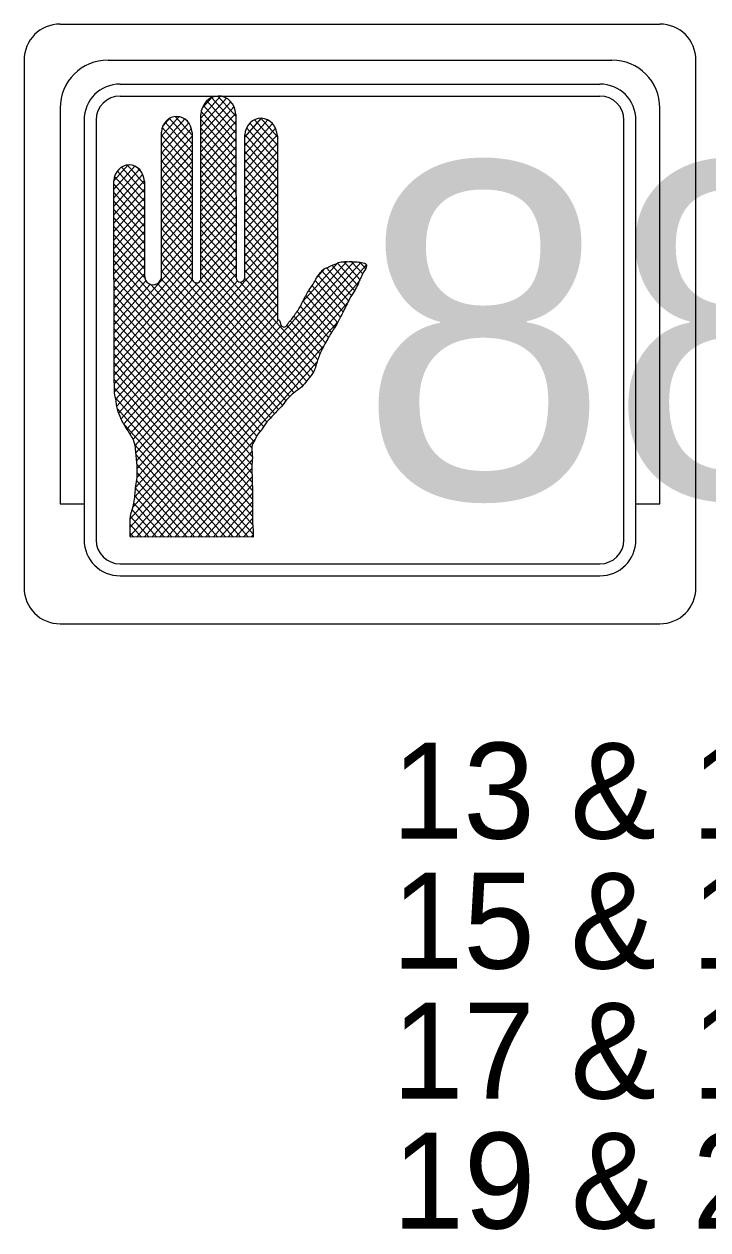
# Model space of a CAD drawing. Extents: x 1281646 to 1282646, y 1891886 to 1892526.
# Drawn here: x 1281920.8 to 1281949.3, y 1892029.8 to 1892080.1 of the extents above; entities that cross this region are included whole.
import ezdxf

# ---------------------------------------------------------------- set-up
doc = ezdxf.new("R2010")
doc.units = 0
doc.layers.add('T_Drafting', color=7, linetype='Continuous')
doc.layers.add('T_Notes', color=7, linetype='Continuous')

msp = doc.modelspace()

# ---------------------------------------------------------------- linework, layer by layer
at = {"layer": 'T_Drafting'}
for p, q in [((1281922.341, 1892080.09), (1281947.341, 1892080.09)), ((1281920.841, 1892078.59), (1281920.841, 1892056.59)), ((1281924.341, 1892078.59), (1281945.341, 1892078.59)), ((1281948.841, 1892056.59), (1281948.841, 1892078.59)), ((1281924.841, 1892077.59), (1281944.841, 1892077.59)), ((1281924.841, 1892077.09), (1281944.841, 1892077.09)), ((1281928.205, 1892076.174), (1281929.027, 1892077.087)), ((1281928.913, 1892077.093), (1281929.668, 1892076.254)), ((1281922.341, 1892076.59), (1281922.341, 1892060.09)), ((1281928.205, 1892075.821), (1281929.27, 1892077.004)), ((1281928.206, 1892075.468), (1281929.455, 1892076.856)), ((1281928.206, 1892075.115), (1281929.589, 1892076.651)), ((1281928.259, 1892076.587), (1281928.66, 1892077.033)), ((1281928.311, 1892076.702), (1281929.67, 1892075.192)), ((1281928.456, 1892076.894), (1281929.669, 1892075.546)), ((1281928.652, 1892077.029), (1281929.669, 1892075.9)), ((1281929.38, 1892076.928), (1281929.521, 1892076.771)), ((1281947.341, 1892060.09), (1281947.341, 1892076.59)), ((1281923.341, 1892076.09), (1281923.341, 1892058.59)), ((1281923.841, 1892076.09), (1281923.841, 1892058.59)), ((1281926.567, 1892075.414), (1281927.304, 1892076.234)), ((1281926.567, 1892075.061), (1281927.536, 1892076.138)), ((1281926.624, 1892075.832), (1281926.935, 1892076.177)), ((1281926.894, 1892076.154), (1281927.84, 1892075.103)), ((1281927.136, 1892076.239), (1281927.84, 1892075.457)), ((1281927.561, 1892076.12), (1281927.73, 1892075.932)), ((1281928.213, 1892069.489), (1281928.205, 1892076.316)), ((1281928.205, 1892076.112), (1281929.67, 1892074.484)), ((1281928.207, 1892074.762), (1281929.664, 1892076.381)), ((1281928.22, 1892076.449), (1281929.67, 1892074.838)), ((1281929.668, 1892076.335), (1281929.676, 1892069.557)), ((1281930.035, 1892075.379), (1281930.741, 1892076.163)), ((1281930.036, 1892075.026), (1281930.998, 1892076.095)), ((1281930.442, 1892076.101), (1281931.397, 1892075.041)), ((1281930.704, 1892076.164), (1281931.396, 1892075.395)), ((1281945.841, 1892058.59), (1281945.841, 1892076.09)), ((1281946.341, 1892058.59), (1281946.341, 1892076.09)), ((1281926.573, 1892069.617), (1281926.567, 1892075.582)), ((1281926.568, 1892074.708), (1281927.705, 1892075.972)), ((1281926.568, 1892074.355), (1281927.813, 1892075.739)), ((1281926.602, 1892075.772), (1281927.841, 1892074.395)), ((1281926.719, 1892075.996), (1281927.841, 1892074.749)), ((1281928.206, 1892075.758), (1281929.671, 1892074.13)), ((1281928.207, 1892074.409), (1281929.669, 1892076.033)), ((1281928.207, 1892074.055), (1281929.669, 1892075.679)), ((1281930.036, 1892074.673), (1281931.187, 1892075.952)), ((1281930.036, 1892074.32), (1281931.323, 1892075.749)), ((1281930.112, 1892075.761), (1281931.397, 1892074.333)), ((1281930.25, 1892075.961), (1281931.397, 1892074.687)), ((1281926.567, 1892075.457), (1281927.842, 1892074.041)), ((1281926.567, 1892075.103), (1281927.842, 1892073.687)), ((1281926.568, 1892074.002), (1281927.84, 1892075.415)), ((1281927.839, 1892075.568), (1281927.846, 1892069.522)), ((1281928.206, 1892075.404), (1281929.671, 1892073.776)), ((1281928.208, 1892073.702), (1281929.669, 1892075.326)), ((1281930.042, 1892069.525), (1281930.035, 1892075.473)), ((1281930.036, 1892075.139), (1281931.398, 1892073.625)), ((1281930.037, 1892075.491), (1281931.398, 1892073.979)), ((1281930.037, 1892073.967), (1281931.394, 1892075.474)), ((1281930.037, 1892073.614), (1281931.397, 1892075.124)), ((1281931.396, 1892075.426), (1281931.405, 1892067.769)), ((1281926.568, 1892074.749), (1281927.842, 1892073.333)), ((1281926.569, 1892073.649), (1281927.84, 1892075.062)), ((1281926.569, 1892073.296), (1281927.841, 1892074.709)), ((1281928.206, 1892075.05), (1281929.672, 1892073.422)), ((1281928.207, 1892074.696), (1281929.672, 1892073.068)), ((1281928.208, 1892073.349), (1281929.67, 1892074.973)), ((1281928.209, 1892072.996), (1281929.67, 1892074.62)), ((1281930.036, 1892074.785), (1281931.398, 1892073.271)), ((1281930.038, 1892073.261), (1281931.397, 1892074.771)), ((1281924.579, 1892073.559), (1281925.174, 1892074.221)), ((1281924.579, 1892073.206), (1281925.449, 1892074.173)), ((1281924.899, 1892074.129), (1281925.852, 1892073.069)), ((1281925.138, 1892074.217), (1281925.852, 1892073.423)), ((1281925.541, 1892074.122), (1281925.763, 1892073.876)), ((1281926.568, 1892074.395), (1281927.843, 1892072.979)), ((1281926.57, 1892072.943), (1281927.841, 1892074.356)), ((1281928.207, 1892074.342), (1281929.672, 1892072.714)), ((1281928.209, 1892072.643), (1281929.671, 1892074.267)), ((1281930.036, 1892074.431), (1281931.399, 1892072.917)), ((1281930.037, 1892074.077), (1281931.399, 1892072.563)), ((1281930.038, 1892072.907), (1281931.397, 1892074.418)), ((1281930.038, 1892072.554), (1281931.398, 1892074.065)), ((1281924.588, 1892065.318), (1281924.578, 1892073.561)), ((1281924.579, 1892072.853), (1281925.645, 1892074.037)), ((1281924.58, 1892072.5), (1281925.783, 1892073.836)), ((1281924.58, 1892072.146), (1281925.851, 1892073.559)), ((1281924.611, 1892073.741), (1281925.853, 1892072.361)), ((1281924.725, 1892073.968), (1281925.853, 1892072.715)), ((1281926.568, 1892074.041), (1281927.843, 1892072.625)), ((1281926.569, 1892073.687), (1281927.844, 1892072.271)), ((1281926.57, 1892072.59), (1281927.842, 1892074.002)), ((1281926.57, 1892072.236), (1281927.842, 1892073.649)), ((1281928.208, 1892073.988), (1281929.673, 1892072.36)), ((1281928.208, 1892073.634), (1281929.673, 1892072.006)), ((1281928.209, 1892072.29), (1281929.671, 1892073.914)), ((1281928.21, 1892071.937), (1281929.671, 1892073.561)), ((1281930.037, 1892073.723), (1281931.4, 1892072.209)), ((1281930.039, 1892072.201), (1281931.398, 1892073.711)), ((1281924.579, 1892073.424), (1281925.854, 1892072.007)), ((1281924.579, 1892073.07), (1281925.854, 1892071.653)), ((1281924.581, 1892071.793), (1281925.852, 1892073.206)), ((1281925.852, 1892073.547), (1281925.856, 1892069.616)), ((1281926.569, 1892073.333), (1281927.844, 1892071.917)), ((1281926.571, 1892071.883), (1281927.842, 1892073.296)), ((1281928.208, 1892073.28), (1281929.674, 1892071.652)), ((1281928.21, 1892071.584), (1281929.672, 1892073.208)), ((1281930.038, 1892073.369), (1281931.4, 1892071.855)), ((1281930.039, 1892071.848), (1281931.398, 1892073.358)), ((1281924.58, 1892072.716), (1281925.854, 1892071.299)), ((1281924.581, 1892071.44), (1281925.853, 1892072.853)), ((1281926.57, 1892072.979), (1281927.844, 1892071.563)), ((1281926.57, 1892072.625), (1281927.845, 1892071.209)), ((1281926.571, 1892071.53), (1281927.843, 1892072.943)), ((1281926.572, 1892071.177), (1281927.843, 1892072.59)), ((1281928.209, 1892072.926), (1281929.674, 1892071.298)), ((1281928.209, 1892072.572), (1281929.674, 1892070.944)), ((1281928.211, 1892071.231), (1281929.672, 1892072.854)), ((1281930.038, 1892073.015), (1281931.4, 1892071.501)), ((1281930.038, 1892072.661), (1281931.401, 1892071.147)), ((1281930.04, 1892071.495), (1281931.399, 1892073.005)), ((1281930.04, 1892071.142), (1281931.399, 1892072.652)), ((1281924.58, 1892072.362), (1281925.855, 1892070.945)), ((1281924.581, 1892071.087), (1281925.853, 1892072.5)), ((1281924.582, 1892070.734), (1281925.853, 1892072.147)), ((1281926.57, 1892072.271), (1281927.845, 1892070.855)), ((1281926.572, 1892070.824), (1281927.844, 1892072.237)), ((1281928.21, 1892072.218), (1281929.675, 1892070.59)), ((1281928.211, 1892070.877), (1281929.673, 1892072.501)), ((1281928.211, 1892070.524), (1281929.673, 1892072.148)), ((1281930.039, 1892072.307), (1281931.401, 1892070.793)), ((1281930.04, 1892070.789), (1281931.399, 1892072.299)), ((1281924.58, 1892072.008), (1281925.855, 1892070.591)), ((1281924.581, 1892071.654), (1281925.856, 1892070.237)), ((1281924.582, 1892070.381), (1281925.854, 1892071.794)), ((1281926.571, 1892071.917), (1281927.846, 1892070.501)), ((1281926.571, 1892071.563), (1281927.846, 1892070.147)), ((1281926.572, 1892070.471), (1281927.844, 1892071.884)), ((1281928.21, 1892071.864), (1281929.675, 1892070.236)), ((1281928.212, 1892070.171), (1281929.673, 1892071.795)), ((1281930.039, 1892071.953), (1281931.401, 1892070.439)), ((1281930.04, 1892071.599), (1281931.402, 1892070.085)), ((1281930.041, 1892070.436), (1281931.4, 1892071.946)), ((1281930.041, 1892070.083), (1281931.4, 1892071.592)), ((1281924.581, 1892071.3), (1281925.856, 1892069.883)), ((1281924.582, 1892070.028), (1281925.854, 1892071.441)), ((1281924.583, 1892069.674), (1281925.855, 1892071.088)), ((1281926.572, 1892071.209), (1281927.846, 1892069.793)), ((1281926.573, 1892070.118), (1281927.844, 1892071.531)), ((1281926.573, 1892069.765), (1281927.845, 1892071.178)), ((1281928.209, 1892069.461), (1281929.674, 1892071.089)), ((1281928.21, 1892071.51), (1281929.675, 1892069.882)), ((1281928.211, 1892071.156), (1281929.67, 1892069.534)), ((1281928.212, 1892069.818), (1281929.674, 1892071.442)), ((1281930.04, 1892071.245), (1281931.402, 1892069.731)), ((1281930.042, 1892069.729), (1281931.401, 1892071.239)), ((1281924.581, 1892070.946), (1281925.868, 1892069.516)), ((1281924.582, 1892070.592), (1281930.959, 1892063.506)), ((1281924.583, 1892069.321), (1281925.855, 1892070.734)), ((1281924.585, 1892067.203), (1281927.845, 1892070.825)), ((1281924.6, 1892065.097), (1281929.675, 1892070.736)), ((1281924.88, 1892063.641), (1281931.401, 1892070.886)), ((1281926.572, 1892070.855), (1281927.862, 1892069.422)), ((1281928.211, 1892070.802), (1281932.905, 1892065.586)), ((1281930.04, 1892070.891), (1281931.402, 1892069.377)), ((1281924.582, 1892070.238), (1281930.812, 1892063.316)), ((1281924.584, 1892068.968), (1281925.855, 1892070.381)), ((1281924.586, 1892066.849), (1281927.846, 1892070.471)), ((1281924.586, 1892066.496), (1281927.846, 1892070.118)), ((1281924.611, 1892064.756), (1281929.675, 1892070.383)), ((1281925.004, 1892063.425), (1281931.401, 1892070.533)), ((1281925.129, 1892063.21), (1281931.402, 1892070.18)), ((1281925.263, 1892059.117), (1281935.11, 1892070.057)), ((1281925.274, 1892059.482), (1281934.879, 1892070.154)), ((1281925.379, 1892059.952), (1281934.59, 1892070.187)), ((1281925.449, 1892060.384), (1281934.272, 1892070.187)), ((1281926.572, 1892070.501), (1281931.919, 1892064.561)), ((1281926.573, 1892070.147), (1281931.762, 1892064.382)), ((1281928.212, 1892070.448), (1281932.765, 1892065.388)), ((1281928.212, 1892070.094), (1281932.615, 1892065.201)), ((1281930.041, 1892070.537), (1281931.403, 1892069.023)), ((1281930.041, 1892070.183), (1281931.403, 1892068.669)), ((1281932.443, 1892068.508), (1281933.898, 1892070.126)), ((1281933.907, 1892070.13), (1281934.739, 1892069.206)), ((1281934.174, 1892070.187), (1281934.84, 1892069.447)), ((1281934.492, 1892070.187), (1281934.953, 1892069.674)), ((1281934.834, 1892070.161), (1281935.064, 1892069.905)), ((1281924.583, 1892069.884), (1281930.678, 1892063.112)), ((1281924.584, 1892068.615), (1281925.856, 1892070.028)), ((1281924.584, 1892068.262), (1281925.856, 1892069.675)), ((1281924.587, 1892066.143), (1281927.846, 1892069.765)), ((1281924.66, 1892064.456), (1281929.675, 1892070.03)), ((1281924.709, 1892064.158), (1281929.676, 1892069.676)), ((1281925.253, 1892062.994), (1281931.402, 1892069.827)), ((1281926.573, 1892069.793), (1281931.606, 1892064.202)), ((1281928.212, 1892069.74), (1281932.459, 1892065.022)), ((1281930.042, 1892069.829), (1281931.404, 1892068.315)), ((1281933.044, 1892069.53), (1281933.386, 1892069.91)), ((1281933.099, 1892069.613), (1281934.254, 1892068.33)), ((1281933.25, 1892069.799), (1281934.366, 1892068.559)), ((1281933.448, 1892069.933), (1281934.489, 1892068.777)), ((1281933.672, 1892070.038), (1281934.617, 1892068.988)), ((1281924.583, 1892069.53), (1281930.534, 1892062.918)), ((1281924.583, 1892069.176), (1281930.422, 1892062.688)), ((1281924.585, 1892067.909), (1281925.919, 1892069.392)), ((1281924.585, 1892067.556), (1281926.1, 1892069.239)), ((1281924.587, 1892065.79), (1281927.86, 1892069.427)), ((1281924.587, 1892065.437), (1281928.07, 1892069.307)), ((1281924.773, 1892063.875), (1281929.734, 1892069.387)), ((1281925.264, 1892058.764), (1281934.803, 1892069.363)), ((1281925.374, 1892062.775), (1281931.402, 1892069.474)), ((1281925.468, 1892062.526), (1281931.403, 1892069.12)), ((1281926.124, 1892069.231), (1281931.119, 1892063.682)), ((1281926.402, 1892069.277), (1281931.281, 1892063.855)), ((1281926.548, 1892069.468), (1281931.444, 1892064.028)), ((1281927.954, 1892069.32), (1281932.09, 1892064.724)), ((1281928.192, 1892069.409), (1281932.278, 1892064.869)), ((1281929.849, 1892069.336), (1281932.999, 1892065.836)), ((1281930.035, 1892069.483), (1281931.404, 1892067.962)), ((1281932.847, 1892069.186), (1281934.025, 1892067.878)), ((1281932.968, 1892069.405), (1281934.142, 1892068.101)), ((1281924.584, 1892068.822), (1281930.339, 1892062.428)), ((1281925.503, 1892062.212), (1281931.403, 1892068.767)), ((1281932.463, 1892068.552), (1281933.654, 1892067.229)), ((1281932.584, 1892068.772), (1281933.784, 1892067.438)), ((1281932.708, 1892068.988), (1281933.906, 1892067.657)), ((1281924.584, 1892068.468), (1281930.35, 1892062.062)), ((1281924.585, 1892068.114), (1281930.335, 1892061.724)), ((1281925.529, 1892058.705), (1281934.327, 1892068.481)), ((1281925.534, 1892061.892), (1281931.403, 1892068.414)), ((1281925.553, 1892061.56), (1281931.404, 1892068.061)), ((1281932.219, 1892068.116), (1281933.401, 1892066.803)), ((1281932.358, 1892068.316), (1281933.523, 1892067.021)), ((1281924.585, 1892067.76), (1281930.336, 1892061.37)), ((1281925.494, 1892060.787), (1281931.566, 1892067.534)), ((1281925.55, 1892061.203), (1281931.45, 1892067.758)), ((1281925.847, 1892058.705), (1281933.909, 1892067.662)), ((1281931.788, 1892067.534), (1281933.08, 1892066.099)), ((1281931.937, 1892067.722), (1281933.175, 1892066.347)), ((1281932.085, 1892067.911), (1281933.283, 1892066.581)), ((1281924.585, 1892067.406), (1281930.352, 1892060.998)), ((1281924.586, 1892067.052), (1281930.354, 1892060.643)), ((1281924.586, 1892066.698), (1281930.354, 1892060.289)), ((1281926.166, 1892058.706), (1281933.326, 1892066.662)), ((1281924.586, 1892066.344), (1281930.355, 1892059.935)), ((1281924.587, 1892065.99), (1281930.357, 1892059.579)), ((1281924.587, 1892065.636), (1281930.371, 1892059.21)), ((1281926.485, 1892058.706), (1281933.043, 1892065.994)), ((1281924.59, 1892065.28), (1281930.391, 1892058.834)), ((1281924.602, 1892064.912), (1281930.183, 1892058.711)), ((1281924.652, 1892064.504), (1281929.865, 1892058.711)), ((1281924.724, 1892064.07), (1281929.548, 1892058.71)), ((1281925.035, 1892063.371), (1281929.23, 1892058.71)), ((1281925.466, 1892062.538), (1281928.912, 1892058.709)), ((1281926.803, 1892058.706), (1281930.476, 1892062.787)), ((1281925.512, 1892062.134), (1281928.594, 1892058.709)), ((1281927.122, 1892058.707), (1281930.345, 1892062.289)), ((1281925.544, 1892061.745), (1281928.276, 1892058.709)), ((1281927.44, 1892058.707), (1281930.343, 1892061.933)), ((1281927.759, 1892058.708), (1281930.334, 1892061.569)), ((1281925.535, 1892061.047), (1281927.641, 1892058.708)), ((1281925.556, 1892061.378), (1281927.959, 1892058.708)), ((1281928.078, 1892058.708), (1281930.342, 1892061.224)), ((1281925.488, 1892060.746), (1281927.323, 1892058.707)), ((1281928.396, 1892058.709), (1281930.353, 1892060.884)), ((1281928.715, 1892058.709), (1281930.354, 1892060.53)), ((1281922.341, 1892060.09), (1281923.341, 1892060.09)), ((1281925.418, 1892060.116), (1281926.687, 1892058.706)), ((1281925.454, 1892060.431), (1281927.005, 1892058.707)), ((1281929.033, 1892058.71), (1281930.354, 1892060.177)), ((1281946.341, 1892060.09), (1281947.341, 1892060.09)), ((1281925.279, 1892059.564), (1281926.052, 1892058.705)), ((1281925.344, 1892059.846), (1281926.37, 1892058.706)), ((1281929.352, 1892058.71), (1281930.355, 1892059.824)), ((1281925.265, 1892059.227), (1281925.734, 1892058.705)), ((1281929.671, 1892058.71), (1281930.36, 1892059.476)), ((1281929.989, 1892058.711), (1281930.374, 1892059.139)), ((1281925.264, 1892058.874), (1281925.416, 1892058.705)), ((1281925.289, 1892058.704), (1281925.264, 1892058.736)), ((1281930.369, 1892058.711), (1281925.289, 1892058.704)), ((1281930.308, 1892058.711), (1281930.391, 1892058.804)), ((1281930.392, 1892058.705), (1281930.369, 1892058.711)), ((1281924.841, 1892057.59), (1281944.841, 1892057.59)), ((1281924.841, 1892057.09), (1281944.841, 1892057.09)), ((1281922.341, 1892055.09), (1281947.341, 1892055.09))]:
    msp.add_line(p, q, dxfattribs=at)
for centre, radius, start, end in [((1281922.341, 1892078.59), 1.5, 90, 180), ((1281947.341, 1892078.59), 1.5, 0, 90), ((1281924.341, 1892076.59), 2, 90, 180), ((1281945.341, 1892076.59), 2, 0, 90), ((1281924.841, 1892076.09), 1.5, 90, 180), ((1281944.841, 1892076.09), 1.5, 0, 90), ((1281924.841, 1892076.09), 1, 90, 180), ((1281944.841, 1892076.09), 1, 0, 90), ((1281924.841, 1892058.59), 1.5, 180, 270), ((1281924.841, 1892058.59), 1, 180, 270), ((1281944.841, 1892058.59), 1.5, 270, 0), ((1281944.841, 1892058.59), 1, 270, 0), ((1281922.341, 1892056.59), 1.5, 180, 270), ((1281947.341, 1892056.59), 1.5, 270, 0)]:
    msp.add_arc(centre, radius, start, end, dxfattribs=at)
for centre, major_axis, start_param, end_param in [((1281928.937, 1892076.279), (0, -0.814), 1.640121, 4.665593), ((1281927.203, 1892075.534), (0, -0.709), 1.618611, 4.644084), ((1281930.714, 1892075.406), (0, -0.758), 1.597842, 4.623315), ((1281925.215, 1892073.513), (0, -0.709), 1.618611, 4.644084), ((1281926.215, 1892069.617), (0, -0.398), 4.713646, 7.855239), ((1281929.856, 1892069.543), (0, -0.207), 4.624552, 7.766145), ((1281928.03, 1892069.506), (0, -0.204), 4.633755, 7.775348)]:
    msp.add_ellipse(centre, major_axis=major_axis, ratio=0.9, start_param=start_param, end_param=end_param, dxfattribs=at)
for points in [[(1281931.404, 1892067.77), (1281931.455, 1892067.756), (1281931.525, 1892067.601), (1281931.613, 1892067.482), (1281931.665, 1892067.463), (1281931.753, 1892067.482), (1281931.807, 1892067.562), (1281931.965, 1892067.757), (1281932.088, 1892067.915), (1281932.158, 1892068.031), (1281932.228, 1892068.129), (1281932.351, 1892068.305), (1281932.421, 1892068.462), (1281932.526, 1892068.676), (1281932.597, 1892068.795), (1281932.72, 1892069.009), (1281932.86, 1892069.206), (1281932.966, 1892069.401), (1281933.088, 1892069.596), (1281933.195, 1892069.733), (1281933.351, 1892069.891), (1281933.544, 1892069.97), (1281933.651, 1892070.029), (1281933.809, 1892070.086), (1281933.949, 1892070.146), (1281934.162, 1892070.187), (1281934.337, 1892070.187), (1281934.566, 1892070.187), (1281934.777, 1892070.168), (1281935.023, 1892070.129), (1281935.093, 1892070.088), (1281935.11, 1892070.031), (1281935.006, 1892069.777), (1281934.935, 1892069.639), (1281934.866, 1892069.501), (1281934.795, 1892069.346), (1281934.759, 1892069.248), (1281934.619, 1892068.992), (1281934.41, 1892068.641), (1281934.128, 1892068.074), (1281933.777, 1892067.426), (1281933.497, 1892066.976), (1281933.338, 1892066.683), (1281933.198, 1892066.407), (1281933.116, 1892066.19), (1281933.073, 1892066.079), (1281932.916, 1892065.607), (1281932.671, 1892065.274), (1281932.477, 1892065.039), (1281932.197, 1892064.803), (1281932.02, 1892064.666), (1281931.564, 1892064.156), (1281931.16, 1892063.727), (1281930.897, 1892063.432), (1281930.668, 1892063.098), (1281930.554, 1892062.953), (1281930.458, 1892062.748), (1281930.352, 1892062.55), (1281930.352, 1892062.12), (1281930.335, 1892061.734), (1281930.336, 1892061.38), (1281930.353, 1892060.912), (1281930.354, 1892060.462), (1281930.355, 1892059.738), (1281930.373, 1892059.155), (1281930.391, 1892058.939), (1281930.391, 1892058.781), (1281930.391, 1892058.706)], [(1281925.264, 1892058.736), (1281925.263, 1892059.05), (1281925.28, 1892059.577), (1281925.42, 1892060.126), (1281925.489, 1892060.752), (1281925.542, 1892061.104), (1281925.541, 1892061.789), (1281925.487, 1892062.356), (1281925.434, 1892062.649), (1281925.171, 1892063.137), (1281924.888, 1892063.627), (1281924.729, 1892064.038), (1281924.658, 1892064.467), (1281924.604, 1892064.8), (1281924.604, 1892065.014), (1281924.588, 1892065.318)]]:
    msp.add_spline(points, degree=3, dxfattribs=at)

# ---------------------------------------------------------------- texts
msp.add_text('88', height=14, rotation=0.072, dxfattribs=at).set_placement((1281934.805, 1892060.311))
at = {"layer": 'T_Notes'}
for s, p in [('13 & 14', (1281936.173, 1892046.137)), ('15 & 16', (1281936.172, 1892040.719)), ('17 & 18', (1281936.182, 1892035.3)), ('19 & 20', (1281936.2, 1892029.882))]:
    msp.add_text(s, height=4, dxfattribs=at).set_placement(p)

doc.saveas('drawing.dxf')
